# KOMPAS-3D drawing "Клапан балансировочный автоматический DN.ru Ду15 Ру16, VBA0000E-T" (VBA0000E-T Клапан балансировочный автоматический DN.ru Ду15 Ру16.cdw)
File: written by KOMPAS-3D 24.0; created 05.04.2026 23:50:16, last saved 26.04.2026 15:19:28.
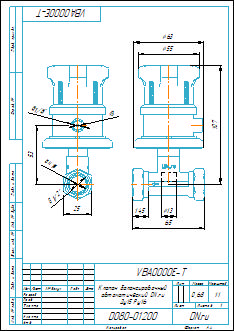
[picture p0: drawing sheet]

Document properties: Автор: tyuri; Форматы листов документа: A4; Полное имя файла: VBA0000E-T Клапан балансировочный автоматический DN.ru Ду15 Ру16.m3d; Масса: 0.675; Наименование: Клапан балансировочный автоматический DN.ru Ду15 Ру16; Количество листов документа: 1; Примечание: D080-01200

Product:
- Body: Тело 6  | qty 1
    Масса: 1.051613
- Part/product: Клапан балансировочный автоматический DN.ru Ду15 Ру16  | designation VBA0000E-T
    Масса: 0.675
    Раздел спецификации: Прочие изделия
    Примечание: D080-01200

Referenced files in D:\Аутсорс\Клапан балансировочный автоматический DN.ru VBA0000E-T Ду15 Ру16\DN15\: VBA0000E-T - Клапан балансировочный автоматический DN.ru Ду15 Ру16.cdw, VBA0000E-T Клапан балансировочный автоматический DN.ru Ду15 Ру16.m3d
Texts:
  Клапан балансировочный
  автоматический DN.ru
  Ду15 Ру16
  VBA0000E-T
  Клапан балансировочный автоматический DN.ru Ду15 Ру16
  VBA0000E-T Клапан балансировочный автоматический DN.ru Ду15 Ру16
Dimensions and other numbers on the sheet: 1:1; 0; 1; 2; 0,68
